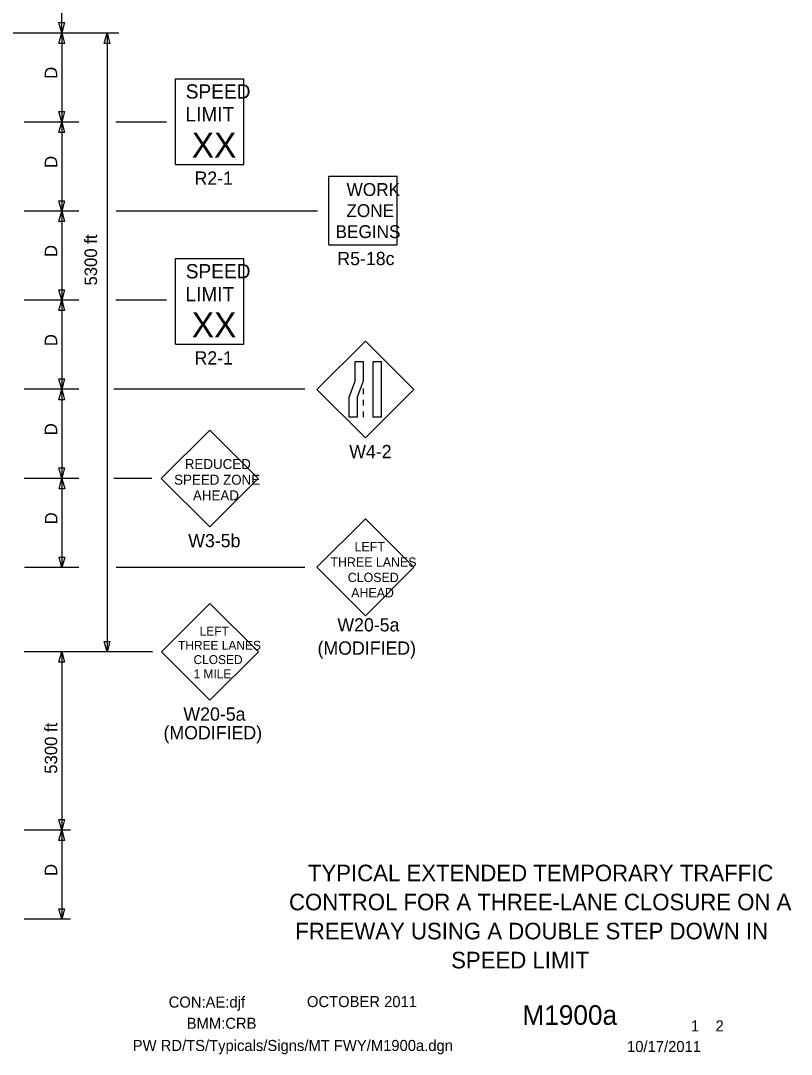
# Model space of a CAD drawing. Extents: x 16725 to 18479, y 5932 to 7023.
# Drawn here: x 17008 to 17440, y 5932 to 6512 of the extents above; entities that cross this region are included whole.
import ezdxf

# ---------------------------------------------------------------- set-up
doc = ezdxf.new("R2010")
doc.units = 0
for name, color, linetype in [('BORDER', 7, 'Continuous'), ('BORDER_SIGNAL_WO', 7, 'Continuous'), ('TRAFFIC_SIGNS_PR', 7, 'Continuous'), ('TYPICAL_TEXT_DIMEN_PR', 7, 'Continuous')]:
    doc.layers.add(name, color=color, linetype=linetype)

msp = doc.modelspace()

# ---------------------------------------------------------------- linework, layer by layer
at = {"layer": 'TRAFFIC_SIGNS_PR'}
for p, q in [((17094.5, 6479.27), (17132.95, 6479.27)), ((17094.5, 6431.21), (17094.5, 6479.27)), ((17132.95, 6431.21), (17132.95, 6479.27)), ((17094.5, 6431.21), (17132.95, 6431.21)), ((17180.53, 6386.1), (17180.53, 6424.5)), ((17180.53, 6424.5), (17218.93, 6424.5)), ((17218.93, 6386.1), (17218.93, 6424.5)), ((17180.53, 6386.1), (17218.93, 6386.1)), ((17094.5, 6378.4), (17132.95, 6378.4)), ((17094.5, 6330.34), (17094.5, 6378.4)), ((17132.95, 6330.34), (17132.95, 6378.4)), ((17094.5, 6330.34), (17132.95, 6330.34)), ((17201.07, 6332.08), (17173.92, 6304.93)), ((17228.22, 6304.93), (17201.07, 6332.08)), ((17173.92, 6304.93), (17201.07, 6277.77)), ((17199.82, 6305.42), (17199.82, 6302.22)), ((17201.07, 6277.77), (17228.22, 6304.93)), ((17199.82, 6299.02), (17199.82, 6295.82)), ((17199.82, 6292.62), (17199.82, 6289.42)), ((17113.71, 6282.11), (17086.56, 6254.95)), ((17140.86, 6254.95), (17113.71, 6282.11)), ((17086.56, 6254.95), (17113.71, 6227.8)), ((17113.71, 6227.8), (17140.86, 6254.95)), ((17201.07, 6232.25), (17173.92, 6205.1)), ((17228.23, 6205.1), (17201.07, 6232.25)), ((17173.92, 6205.1), (17201.07, 6177.95)), ((17201.07, 6177.95), (17228.23, 6205.1)), ((17113.83, 6184.86), (17086.64, 6157.68)), ((17141.02, 6157.68), (17113.83, 6184.86)), ((17086.64, 6157.68), (17113.83, 6130.49)), ((17113.83, 6130.49), (17141.02, 6157.68))]:
    msp.add_line(p, q, dxfattribs=at)
for points in [[(17199.82, 6320.66), (17199.82, 6309.48), (17196.48, 6300.6), (17196.48, 6289.42), (17191.99, 6289.42), (17191.99, 6300.6), (17195.33, 6309.48), (17195.33, 6320.66)], [(17209.96, 6320.66), (17209.96, 6289.42), (17205.47, 6289.42), (17205.47, 6320.66)]]:
    msp.add_lwpolyline(points, close=True, dxfattribs=at)
at = {"layer": 'TYPICAL_TEXT_DIMEN_PR'}
for p, q in [((17030.69, 6504.98), (17030.69, 6535.54)), ((17030.69, 6504.98), (17029.12, 6510.84)), ((17029.12, 6510.84), (17030.69, 6510.84)), ((17030.69, 6510.84), (17032.26, 6510.84)), ((17032.26, 6510.84), (17030.69, 6504.98)), ((16878.96, 6504.98), (17062.74, 6504.98)), ((16907.09, 6504.98), (17061.13, 6504.98)), ((17029.12, 6499.12), (17030.69, 6504.98)), ((17030.69, 6504.98), (17030.69, 6454.98)), ((17030.69, 6504.98), (17032.26, 6499.12)), ((17054.56, 6499.12), (17056.13, 6504.98)), ((17056.13, 6504.98), (17056.13, 6157.67)), ((17056.13, 6504.98), (17057.7, 6499.12)), ((17030.69, 6499.12), (17029.12, 6499.12)), ((17032.26, 6499.12), (17030.69, 6499.12)), ((17056.13, 6499.12), (17054.56, 6499.12)), ((17057.7, 6499.12), (17056.13, 6499.12)), ((17030.69, 6454.98), (17029.12, 6460.84)), ((17029.12, 6460.84), (17030.69, 6460.84)), ((17030.69, 6460.84), (17032.26, 6460.84)), ((17032.26, 6460.84), (17030.69, 6454.98)), ((17040.19, 6454.98), (17009.69, 6454.98)), ((17029.12, 6449.12), (17030.69, 6454.98)), ((17030.69, 6454.98), (17030.69, 6404.98)), ((17030.69, 6454.98), (17032.26, 6449.12)), ((17089.41, 6454.98), (17061.13, 6454.98)), ((17030.69, 6449.12), (17029.12, 6449.12)), ((17032.26, 6449.12), (17030.69, 6449.12)), ((17030.69, 6404.98), (17029.12, 6410.84)), ((17029.12, 6410.84), (17030.69, 6410.84)), ((17030.69, 6410.84), (17032.26, 6410.84)), ((17032.26, 6410.84), (17030.69, 6404.98)), ((17040.19, 6404.98), (17009.69, 6404.98)), ((17029.12, 6399.12), (17030.69, 6404.98)), ((17030.69, 6404.98), (17030.69, 6354.98)), ((17030.69, 6404.98), (17032.26, 6399.12)), ((17174.2, 6404.98), (17061.19, 6404.98)), ((17030.69, 6399.12), (17029.12, 6399.12)), ((17032.26, 6399.12), (17030.69, 6399.12)), ((17030.69, 6354.98), (17029.12, 6360.84)), ((17029.12, 6360.84), (17030.69, 6360.84)), ((17030.69, 6360.84), (17032.26, 6360.84)), ((17032.26, 6360.84), (17030.69, 6354.98)), ((17040.19, 6354.98), (17009.69, 6354.98)), ((17029.12, 6349.12), (17030.69, 6354.98)), ((17030.69, 6354.98), (17030.69, 6304.98)), ((17030.69, 6354.98), (17032.26, 6349.12)), ((17089.41, 6354.98), (17061.13, 6354.98)), ((17030.69, 6349.12), (17029.12, 6349.12)), ((17032.26, 6349.12), (17030.69, 6349.12)), ((17030.69, 6304.98), (17029.12, 6310.84)), ((17029.12, 6310.84), (17030.69, 6310.84)), ((17030.69, 6310.84), (17032.26, 6310.84)), ((17032.26, 6310.84), (17030.69, 6304.98)), ((17040.19, 6304.98), (17009.69, 6304.98)), ((17029.12, 6299.12), (17030.69, 6304.98)), ((17030.69, 6304.98), (17030.69, 6254.98)), ((17030.69, 6304.98), (17032.26, 6299.12)), ((17167.09, 6304.98), (17059.87, 6304.98)), ((17030.69, 6299.12), (17029.12, 6299.12)), ((17032.26, 6299.12), (17030.69, 6299.12)), ((17030.69, 6254.98), (17029.12, 6260.84)), ((17029.12, 6260.84), (17030.69, 6260.84)), ((17030.69, 6260.84), (17032.26, 6260.84)), ((17032.26, 6260.84), (17030.69, 6254.98)), ((17040.19, 6254.98), (17009.69, 6254.98)), ((17029.26, 6249.12), (17030.83, 6254.98)), ((17030.83, 6254.98), (17030.83, 6204.98)), ((17030.83, 6254.98), (17032.4, 6249.12)), ((17081.28, 6254.98), (17059.87, 6254.98)), ((17030.83, 6249.12), (17029.26, 6249.12)), ((17032.4, 6249.12), (17030.83, 6249.12)), ((17030.83, 6204.98), (17029.26, 6210.84)), ((17029.26, 6210.84), (17030.83, 6210.84)), ((17030.83, 6210.84), (17032.4, 6210.84)), ((17032.4, 6210.84), (17030.83, 6204.98)), ((17040.19, 6204.98), (17009.83, 6204.98)), ((17167.09, 6204.98), (17061.19, 6204.98)), ((17056.13, 6157.67), (17054.56, 6163.54)), ((17054.56, 6163.54), (17056.13, 6163.54)), ((17056.13, 6163.54), (17057.7, 6163.54)), ((17057.7, 6163.54), (17056.13, 6157.67)), ((17081.64, 6157.67), (17009.69, 6157.67)), ((17029.12, 6151.81), (17030.69, 6157.67)), ((17030.69, 6157.67), (17030.69, 6057.67)), ((17030.69, 6157.67), (17032.26, 6151.81)), ((17030.69, 6151.81), (17029.12, 6151.81)), ((17032.26, 6151.81), (17030.69, 6151.81)), ((17030.69, 6057.67), (17029.12, 6063.54)), ((17029.12, 6063.54), (17030.69, 6063.54)), ((17030.69, 6063.54), (17032.26, 6063.54)), ((17032.26, 6063.54), (17030.69, 6057.67)), ((17035.69, 6057.67), (17009.69, 6057.67)), ((17029.12, 6051.81), (17030.69, 6057.67)), ((17030.69, 6057.67), (17030.69, 6007.67)), ((17030.69, 6057.67), (17032.26, 6051.81)), ((17030.69, 6051.81), (17029.12, 6051.81)), ((17032.26, 6051.81), (17030.69, 6051.81)), ((17030.69, 6007.67), (17029.12, 6013.54)), ((17029.12, 6013.54), (17030.69, 6013.54)), ((17030.69, 6013.54), (17032.26, 6013.54)), ((17032.26, 6013.54), (17030.69, 6007.67)), ((17035.69, 6007.67), (17009.69, 6007.67))]:
    msp.add_line(p, q, dxfattribs=at)

# ---------------------------------------------------------------- texts
at = {"layer": 'BORDER'}
for s, p in [('TYPICAL EXTENDED TEMPORARY TRAFFIC', (17168.85, 6028.96)), ('CONTROL FOR A THREE-LANE CLOSURE ON A', (17158.22, 6012.66)), ('FREEWAY USING A DOUBLE STEP DOWN IN ', (17161.72, 5996.36)), ('SPEED LIMIT', (17249.22, 5980.06))]:
    msp.add_text(s, height=9.3, dxfattribs=at).set_placement(p)
at = {"layer": 'BORDER_SIGNAL_WO'}
for s, height, p in [('CON:AE:djf  ', 6.2, (17090.69, 5958.06)), ('    OCTOBER 2011', 6.2, (17159.08, 5958.34)), ('    M1900a   ', 11, (17272.86, 5948.38)), ('BMM:CRB', 6.2, (17100.81, 5946.17)), (' 1    2 ', 6.2, (17381.45, 5944.7)), ('PW RD/TS/Typicals/Signs/MT FWY/M1900a.dgn      ', 6.2, (17070.55, 5933.71)), ('10/17/2011', 6.2, (17347.93, 5933.13))]:
    msp.add_text(s, height=height, dxfattribs=at).set_placement(p)
at = {"layer": 'TRAFFIC_SIGNS_PR'}
for s, height, p in [('SPEED', 8.01, (17100.28, 6468.12)), ('LIMIT', 8.01, (17100.12, 6455.31)), ('XX', 14.048, (17103.63, 6434.98)), ('R2-1', 7.449, (17105.19, 6419.76)), ('WORK', 7.217, (17190.53, 6413.47)), ('ZONE', 7.217, (17190.42, 6401.65)), ('BEGINS', 7.217, (17184.34, 6389.85)), ('R5-18c', 7.44, (17185.35, 6374.66)), ('SPEED', 8.01, (17100.28, 6367.24)), ('LIMIT', 8.01, (17100.12, 6354.43)), ('XX', 14.048, (17103.63, 6334.1)), ('R2-1', 7.449, (17105.19, 6318.88)), ('W4-2', 7.44, (17192.03, 6266.34)), ('REDUCED', 5.6, (17099.77, 6260.26)), ('SPEED ZONE', 5.6, (17093.76, 6251.46)), ('AHEAD', 5.6, (17104.32, 6242.66)), ('W3-5b', 7.44, (17101.66, 6216.36)), ('LEFT', 5.2, (17195.02, 6214.04)), ('THREE LANES', 5.2, (17181.47, 6205.44)), ('CLOSED', 5.2, (17191.2, 6196.84)), ('AHEAD', 5.2, (17193.14, 6188.24)), ('LEFT', 5.006, (17108.07, 6166.83)), ('W20-5a', 7.44, (17185.37, 6169.13)), ('THREE LANES', 5.0062, (17095.95, 6158.82)), ('(MODIFIED)', 7.44, (17174.23, 6156.09)), ('CLOSED', 5.006, (17104.65, 6150.81)), ('1 MILE', 5.006, (17104.65, 6142.81)), ('W20-5a', 7.449, (17098.95, 6119.04)), ('(MODIFIED)', 7.449, (17087.79, 6108.59))]:
    msp.add_text(s, height=height, dxfattribs=at).set_placement(p)
at = {"layer": 'TYPICAL_TEXT_DIMEN_PR'}
for s, p in [('D', (17028.14, 6479.2)), ('D', (17028.14, 6429.2)), ('5300 ft', (17050.5, 6363.23)), ('D', (17028.14, 6379.2)), ('D', (17028.14, 6329.2)), ('D', (17028.14, 6279.2)), ('D', (17028.27, 6229.2)), ('5300 ft', (17028.14, 6089.28)), ('D', (17028.14, 6031.89))]:
    msp.add_text(s, height=7, rotation=90, dxfattribs=at).set_placement(p)

doc.saveas('drawing.dxf')
